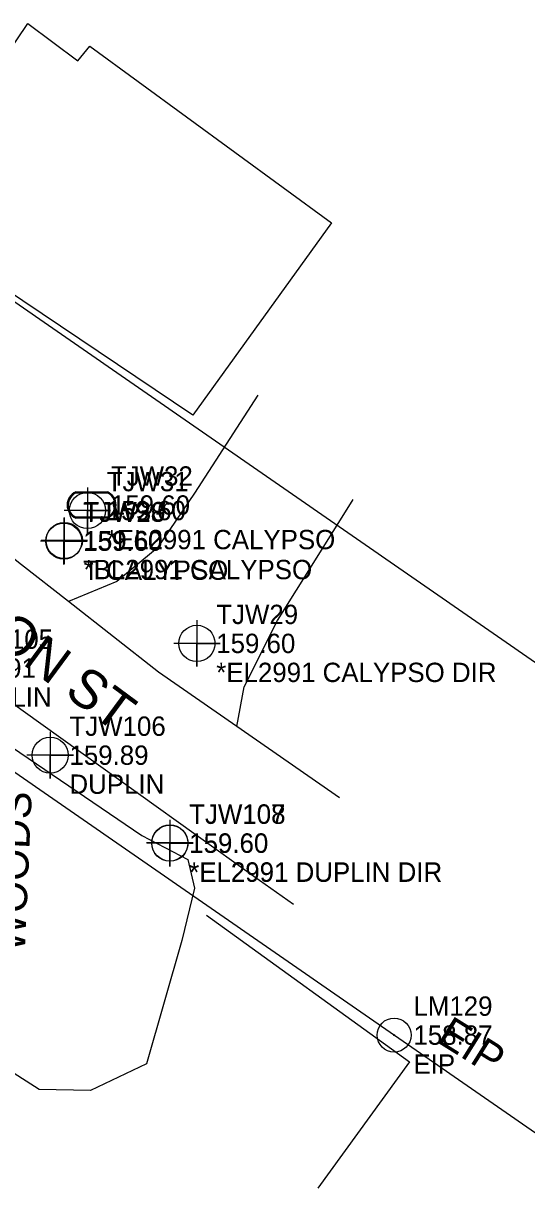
# Model space of a CAD drawing. Extents: x 2262665 to 2270527, y 505476 to 514960.
# Drawn here: x 2266595.3 to 2266660.4, y 511484.8 to 511636.3 of the extents above; entities that cross this region are included whole.
import ezdxf

# ---------------------------------------------------------------- set-up
doc = ezdxf.new("R2010")
doc.units = 0
for name, color, linetype in [('Exist Building', 7, 'Continuous'), ('Exist Other Culture Fence Line', 7, 'Continuous'), ('Exist Property Iron Pin CELL', 7, 'Continuous'), ('Exist Property Iron Pin Cogo Comment', 7, 'Continuous'), ('Exist Property Iron Pin Cogo Elevation', 7, 'Continuous'), ('Exist Property Iron Pin Cogo Number', 7, 'Continuous'), ('Exist Property Iron Pin Text', 7, 'Continuous'), ('Exist Right of Way Line', 7, 'Continuous'), ('Exist Roads EOP', 7, 'Continuous'), ('Exist Roads EOP Text', 7, 'Continuous'), ('Exist Roads Soil', 7, 'Continuous'), ('Exist Utilities Water Meter CELL', 7, 'Continuous'), ('Exist Utilities Water Meter Cogo Elevation', 7, 'Continuous'), ('Exist Utilities Water Meter Cogo Number', 7, 'Continuous'), ('Exist Utilities Water UG Line SUE LOS B Cogo Comment', 7, 'Continuous'), ('Exist Utilities Water UG Line SUE LOS B Cogo Elevation', 7, 'Continuous'), ('Exist Utilities Water UG Line SUE LOS B Cogo Number', 7, 'Continuous'), ('Exist Utilities Water UG Line SUE LOS B Cogo Point CELL', 7, 'Continuous'), ('Exist Vegetation Woods Line', 7, 'Continuous'), ('Exist Vegetation Woods Line Text', 7, 'Continuous')]:
    doc.layers.add(name, color=color, linetype=linetype)

msp = doc.modelspace()

# ---------------------------------------------------------------- linework, layer by layer
at = {"layer": 'Exist Building'}
msp.add_lwpolyline([(2266617.19, 511585.64), (2266585.43, 511606.98), (2266586.75, 511609.48), (2266580.77, 511613.97), (2266595.88, 511636.33), (2266602.35, 511631.48), (2266603.91, 511633.4), (2266635.16, 511610.53)], close=True, dxfattribs=at)
at = {"layer": 'Exist Other Culture Fence Line'}
msp.add_lwpolyline([(2266618.97, 511520.98), (2266645.25, 511502), (2266633.39, 511485.66)], dxfattribs=at)
at = {"layer": 'Exist Property Iron Pin CELL'}
for radius in [2.2, 0.0707]:
    msp.add_circle((2266643.24, 511505.46), radius, dxfattribs=at)
at = {"layer": 'Exist Right of Way Line'}
for p, q in [((2266563.3, 511621.69), (2266851.09, 511422.27)), ((2266538.53, 511578.02), (2266823.18, 511380.77))]:
    msp.add_line(p, q, dxfattribs=at)
at = {"layer": 'Exist Roads EOP'}
for points in [[(2266636.19, 511536.16), (2266629.55, 511540.77), (2266622.91, 511545.37), (2266612.77, 511552.4), (2266612.77, 511552.4), (2266606.95, 511556.96), (2266601.13, 511561.53), (2266595.07, 511566.28), (2266589.01, 511571.04), (2266582.95, 511575.79), (2266575.45, 511581.56), (2266567.95, 511587.32), (2266560.45, 511593.09), (2266552.28, 511600.44)], [(2266540.99, 511585.41), (2266542.82, 511585), (2266543.07, 511584.82), (2266550.53, 511579.47), (2266557.98, 511574.13), (2266565.44, 511568.78), (2266572.9, 511563.43), (2266580.36, 511558.09), (2266587.82, 511552.74), (2266595.28, 511547.39), (2266602.74, 511542.04), (2266610.2, 511536.7), (2266617.65, 511531.35), (2266625.11, 511526)], [(2266625.11, 511526), (2266630.25, 511522.39)]]:
    msp.add_lwpolyline(points, dxfattribs=at)
at = {"layer": 'Exist Roads Soil'}
for points in [[(2266625.6, 511588.23), (2266621.51, 511581.9), (2266617.42, 511575.57), (2266612.58, 511568.44), (2266607.37, 511564.13), (2266601.13, 511561.53)], [(2266622.91, 511545.37), (2266623.84, 511550.53), (2266628.18, 511559.09), (2266633.06, 511566.92), (2266637.95, 511574.76)]]:
    msp.add_lwpolyline(points, dxfattribs=at)
at = {"layer": 'Exist Utilities Water Meter CELL'}
msp.add_line((2266604.12, 511574.03), (2266604.12, 511574.03), dxfattribs=at)
for points in [[(2266602.09, 511575.73), (2266606.16, 511575.73)], [(2266602.09, 511575.59), (2266606.16, 511575.59)], [(2266606.16, 511572.46), (2266602.06, 511572.46)], [(2266606.16, 511572.33), (2266602.06, 511572.33)]]:
    msp.add_lwpolyline(points, dxfattribs=at)
for centre, radius, start, end in [((2266602.82, 511574.02), 1.86, 113.178, 245.9794), ((2266605.42, 511574.03), 1.86, 293.6483, 66.3084), ((2266602.83, 511574.02), 1.73, 115.3009, 243.7824), ((2266605.43, 511574.03), 1.73, 295.1272, 64.8728)]:
    msp.add_arc(centre, radius, start, end, dxfattribs=at)
at = {"layer": 'Exist Utilities Water UG Line SUE LOS B Cogo Point CELL'}
for points in [[(2266603.58, 511576.31), (2266603.58, 511570.31), (2266603.58, 511573.31), (2266606.58, 511573.31), (2266600.58, 511573.31)], [(2266600.53, 511572.35), (2266600.53, 511566.35), (2266600.53, 511569.35), (2266603.53, 511569.35), (2266597.53, 511569.35)], [(2266600.59, 511572.43), (2266600.59, 511566.43), (2266600.59, 511569.43), (2266603.59, 511569.43), (2266597.59, 511569.43)], [(2266617.74, 511559.13), (2266617.74, 511553.13), (2266617.74, 511556.13), (2266620.74, 511556.13), (2266614.74, 511556.13)], [(2266598.76, 511544.67), (2266598.76, 511538.67), (2266598.76, 511541.67), (2266601.76, 511541.67), (2266595.76, 511541.67)], [(2266614.24, 511533.31), (2266614.24, 511527.31), (2266614.24, 511530.31), (2266617.24, 511530.31), (2266611.24, 511530.31)], [(2266614.25, 511533.28), (2266614.25, 511527.28), (2266614.25, 511530.28), (2266617.25, 511530.28), (2266611.25, 511530.28)]]:
    msp.add_lwpolyline(points, dxfattribs=at)
for centre in [(2266603.58, 511573.31), (2266600.53, 511569.35), (2266600.59, 511569.43), (2266617.74, 511556.13), (2266598.76, 511541.67), (2266614.24, 511530.31), (2266614.25, 511530.28)]:
    msp.add_circle(centre, 2.34, dxfattribs=at)
at = {"layer": 'Exist Vegetation Woods Line'}
msp.add_lwpolyline([(2266546.54, 511574.87), (2266610.6, 511531.26), (2266616.57, 511528.17), (2266617.43, 511524.45), (2266615.81, 511517.7), (2266611.23, 511501.76), (2266604, 511498.31), (2266597.32, 511498.41), (2266591.8, 511501.94)], dxfattribs=at)

# ---------------------------------------------------------------- texts
at = {"layer": 'Exist Property Iron Pin Cogo Comment'}
msp.add_text('EIP', height=2.5, dxfattribs=at).set_placement((2266645.74, 511500.46))
at = {"layer": 'Exist Property Iron Pin Cogo Elevation'}
msp.add_text('158.87', height=2.5, dxfattribs=at).set_placement((2266645.74, 511504.21))
at = {"layer": 'Exist Property Iron Pin Cogo Number'}
msp.add_text('LM129', height=2.5, dxfattribs=at).set_placement((2266645.74, 511507.96))
at = {"layer": 'Exist Property Iron Pin Text'}
msp.add_text('EIP', height=4, rotation=327.9858, dxfattribs=at).set_placement((2266648.58, 511504.65))
at = {"layer": 'Exist Roads EOP Text'}
msp.add_text('W CAMERON ST', height=5, rotation=323.5473, dxfattribs=at).set_placement((2266564.89, 511575.79))
at = {"layer": 'Exist Utilities Water Meter Cogo Elevation'}
msp.add_text('159.60', height=2.5, dxfattribs=at).set_placement((2266606.62, 511572.78))
at = {"layer": 'Exist Utilities Water Meter Cogo Number'}
msp.add_text('TJW32', height=2.5, dxfattribs=at).set_placement((2266606.62, 511576.53))
at = {"layer": 'Exist Utilities Water UG Line SUE LOS B Cogo Comment'}
for s, p in [('*EL2991 CALYPSO', (2266606.08, 511568.31)), ('T CALYPSO', (2266603.03, 511564.35)), ('*BL2991 CALYPSO', (2266603.09, 511564.43)), ('*EL2991 CALYPSO DIR', (2266620.24, 511551.13)), ('DUPLIN', (2266586.69, 511547.93)), ('DUPLIN', (2266601.26, 511536.67)), ('*EL2991 DUPLIN DIR', (2266616.74, 511525.31)), ('*EL2991 DUPLIN DIR', (2266616.75, 511525.28))]:
    msp.add_text(s, height=2.5, dxfattribs=at).set_placement(p)
at = {"layer": 'Exist Utilities Water UG Line SUE LOS B Cogo Elevation'}
for s, p in [('159.60', (2266606.08, 511572.06)), ('159.60', (2266603.03, 511568.1)), ('159.60', (2266603.09, 511568.18)), ('159.60', (2266620.24, 511554.88)), ('159.91', (2266586.69, 511551.68)), ('159.89', (2266601.26, 511540.42)), ('159.60', (2266616.74, 511529.06)), ('159.60', (2266616.75, 511529.03))]:
    msp.add_text(s, height=2.5, dxfattribs=at).set_placement(p)
at = {"layer": 'Exist Utilities Water UG Line SUE LOS B Cogo Number'}
for s, p in [('TJW31', (2266606.08, 511575.81)), ('TJW28', (2266603.03, 511571.85)), ('TJW30', (2266603.09, 511571.93)), ('TJW29', (2266620.24, 511558.63)), ('TJW105', (2266586.69, 511555.43)), ('TJW106', (2266601.26, 511544.17)), ('TJW107', (2266616.74, 511532.81)), ('TJW108', (2266616.75, 511532.78))]:
    msp.add_text(s, height=2.5, dxfattribs=at).set_placement(p)
at = {"layer": 'Exist Vegetation Woods Line Text'}
msp.add_text('WOODS', height=4, rotation=87.4803, dxfattribs=at).set_placement((2266595.48, 511516.13))

doc.saveas('drawing.dxf')
